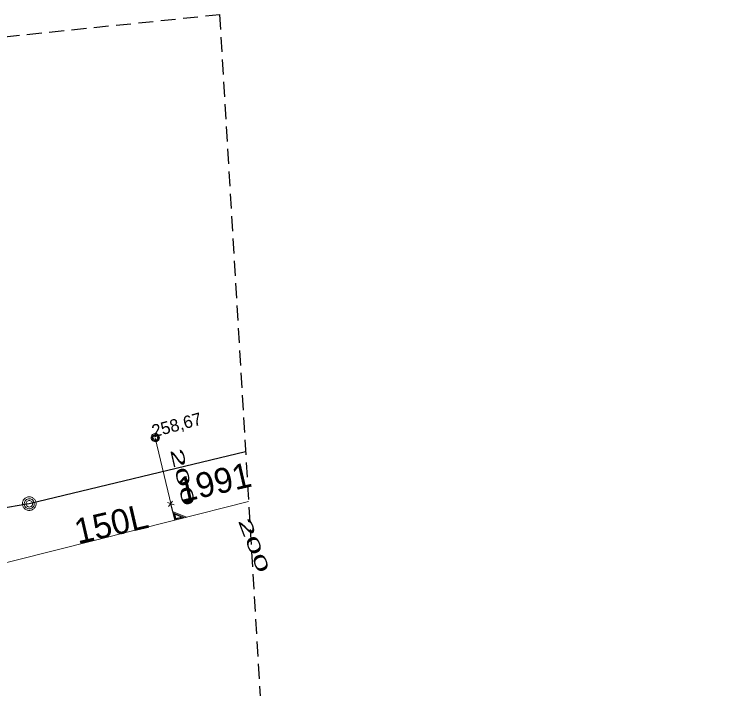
# Model space of a CAD drawing. Extents: x -732096 to -731933, y -1048703 to -1047964.
# Drawn here: x -732014.98 to -731968.39, y -1048007.32 to -1047964.04 of the extents above; entities that cross this region are included whole.
import ezdxf

# ---------------------------------------------------------------- set-up
doc = ezdxf.new("R2010")
doc.units = 0
doc.header["$LTSCALE"] = 0.32
doc.linetypes.add('MEDIUM_DASHED', pattern=[4.5, 3, -1.5])
doc.layers.add('1', color=7, linetype='Continuous')
for name, color, linetype, lineweight in [('18', 7, 'Continuous', 13), ('20', 7, 'Continuous', 13), ('49', 7, 'Continuous', 13), ('63', 7, 'MEDIUM_DASHED', 25), ('8', 7, 'Continuous', 13)]:
    doc.layers.add(name, color=color, linetype=linetype, lineweight=lineweight)

msp = doc.modelspace()

# ---------------------------------------------------------------- linework, layer by layer
at = {"layer": '18'}
for p, q in [((-732005.165, -1047995.377), (-732004.745, -1047995.523)), ((-732004.839, -1047995.281), (-732005.098, -1047995.624))]:
    msp.add_line(p, q, dxfattribs=at)
for points in [[(-732005.685, -1047991.207), (-732005.691, -1047991.151), (-732005.708, -1047991.098), (-732005.737, -1047991.049), (-732005.775, -1047991.008), (-732005.821, -1047990.976), (-732005.873, -1047990.954), (-732005.928, -1047990.943), (-732005.984, -1047990.945), (-732006.039, -1047990.958), (-732006.09, -1047990.983), (-732006.134, -1047991.018), (-732006.17, -1047991.061), (-732006.195, -1047991.111), (-732006.21, -1047991.166), (-732006.213, -1047991.222), (-732006.204, -1047991.277), (-732006.183, -1047991.33), (-732006.152, -1047991.376), (-732006.112, -1047991.415), (-732006.064, -1047991.445), (-732006.011, -1047991.464), (-732005.955, -1047991.471), (-732005.899, -1047991.467), (-732005.845, -1047991.45), (-732005.796, -1047991.423), (-732005.754, -1047991.385), (-732005.721, -1047991.34), (-732005.698, -1047991.289), (-732005.686, -1047991.234)], [(-732005.744, -1047991.21), (-732005.75, -1047991.161), (-732005.768, -1047991.115), (-732005.796, -1047991.074), (-732005.833, -1047991.041), (-732005.877, -1047991.019), (-732005.925, -1047991.007), (-732005.974, -1047991.007), (-732006.022, -1047991.019), (-732006.066, -1047991.042), (-732006.103, -1047991.075), (-732006.131, -1047991.116), (-732006.148, -1047991.163), (-732006.154, -1047991.212), (-732006.147, -1047991.261), (-732006.129, -1047991.307), (-732006.101, -1047991.347), (-732006.064, -1047991.38), (-732006.02, -1047991.402), (-732005.971, -1047991.414), (-732005.922, -1047991.413), (-732005.874, -1047991.401), (-732005.831, -1047991.377), (-732005.794, -1047991.344), (-732005.766, -1047991.303), (-732005.75, -1047991.256)], [(-732005.803, -1047991.214), (-732005.809, -1047991.172), (-732005.826, -1047991.134), (-732005.854, -1047991.103), (-732005.889, -1047991.08), (-732005.929, -1047991.069), (-732005.971, -1047991.069), (-732006.011, -1047991.081), (-732006.046, -1047991.104), (-732006.073, -1047991.136), (-732006.09, -1047991.174), (-732006.095, -1047991.215), (-732006.089, -1047991.257), (-732006.071, -1047991.294), (-732006.043, -1047991.326), (-732006.007, -1047991.348), (-732005.967, -1047991.359), (-732005.925, -1047991.358), (-732005.885, -1047991.345), (-732005.851, -1047991.322), (-732005.824, -1047991.289), (-732005.808, -1047991.251)]]:
    msp.add_lwpolyline(points, close=True, dxfattribs=at)
for points in [[(-732004.964, -1047995.446), (-732004.695, -1047996.509), (-732003.948, -1047996.32), (-732004.837, -1047995.948)], [(-732004.758, -1047996.05), (-732004.657, -1047996.453), (-732004.109, -1047996.315), (-732004.759, -1047996.049)], [(-732004.692, -1047996.12), (-732004.621, -1047996.402), (-732004.261, -1047996.311), (-732004.694, -1047996.121)]]:
    msp.add_lwpolyline(points, dxfattribs=at)
at = {"layer": '20'}
msp.add_lwpolyline([(-732017.52, -1047999.75), (-732004.701, -1047996.513), (-731999.955, -1047995.314)], dxfattribs=at)
msp.add_lwpolyline([(-732017.52, -1047999.75), (-732004.701, -1047996.513), (-731999.955, -1047995.314)], dxfattribs=at)
at = {"layer": '49'}
msp.add_line((-732005.949, -1047991.22), (-732004.701, -1047996.513), dxfattribs=at)
msp.add_line((-732005.949, -1047991.22), (-732004.701, -1047996.513), dxfattribs=at)
at = {"layer": '63'}
msp.add_lwpolyline([(-732040.436, -1048145.923), (-732073.567, -1048047.117), (-732073.568, -1048047.115), (-732073.568, -1048047.114), (-732073.568, -1048047.112), (-732060.033, -1047970.086), (-732060.033, -1047970.084), (-732060.032, -1047970.082), (-732060.031, -1047970.081), (-732060.029, -1047970.079), (-732060.028, -1047970.078), (-732060.026, -1047970.078), (-732060.024, -1047970.077), (-732001.831, -1047964.038), (-732001.829, -1047964.038), (-732001.827, -1047964.038), (-732001.825, -1047964.039), (-732001.823, -1047964.04), (-732001.822, -1047964.041), (-732001.821, -1047964.043), (-732001.82, -1047964.045), (-732001.82, -1047964.047), (-731997.077, -1048043.55), (-731968.389, -1048129.387)], dxfattribs=at)
at = {"layer": '8', "lineweight": 25}
for p, q in [((-732000.146, -1047992.114), (-732014.03, -1047995.459)), ((-732014.03, -1047995.459), (-732033.089, -1047998.739))]:
    msp.add_line(p, q, dxfattribs=at)
at = {"layer": '8'}
msp.add_lwpolyline([(-732013.598, -1047995.448), (-732013.601, -1047995.403), (-732013.608, -1047995.358), (-732013.62, -1047995.313), (-732013.636, -1047995.271), (-732013.657, -1047995.23), (-732013.682, -1047995.191), (-732013.711, -1047995.156), (-732013.743, -1047995.123), (-732013.779, -1047995.095), (-732013.816, -1047995.07), (-732013.858, -1047995.049), (-732013.901, -1047995.032), (-732013.945, -1047995.02), (-732013.99, -1047995.013), (-732014.036, -1047995.011), (-732014.081, -1047995.013), (-732014.127, -1047995.02), (-732014.171, -1047995.032), (-732014.214, -1047995.049), (-732014.255, -1047995.07), (-732014.293, -1047995.095), (-732014.329, -1047995.123), (-732014.361, -1047995.156), (-732014.39, -1047995.191), (-732014.415, -1047995.23), (-732014.436, -1047995.271), (-732014.451, -1047995.313), (-732014.464, -1047995.358), (-732014.471, -1047995.403), (-732014.473, -1047995.449), (-732014.471, -1047995.494), (-732014.464, -1047995.539), (-732014.451, -1047995.584), (-732014.436, -1047995.626), (-732014.415, -1047995.667), (-732014.39, -1047995.706), (-732014.361, -1047995.741), (-732014.329, -1047995.774), (-732014.293, -1047995.802), (-732014.255, -1047995.827), (-732014.214, -1047995.848), (-732014.171, -1047995.865), (-732014.127, -1047995.876), (-732014.081, -1047995.884), (-732014.036, -1047995.886), (-732013.99, -1047995.884), (-732013.945, -1047995.876), (-732013.901, -1047995.865), (-732013.858, -1047995.848), (-732013.816, -1047995.827), (-732013.779, -1047995.802), (-732013.743, -1047995.774), (-732013.711, -1047995.741), (-732013.682, -1047995.706), (-732013.657, -1047995.667), (-732013.636, -1047995.626), (-732013.62, -1047995.584), (-732013.608, -1047995.539), (-732013.601, -1047995.494), (-732013.598, -1047995.449)], dxfattribs=at)
for points in [[(-732013.712, -1047995.456), (-732013.718, -1047995.395), (-732013.736, -1047995.335), (-732013.765, -1047995.28), (-732013.804, -1047995.232), (-732013.851, -1047995.192), (-732013.905, -1047995.162), (-732013.964, -1047995.142), (-732014.026, -1047995.135), (-732014.088, -1047995.139), (-732014.147, -1047995.155), (-732014.203, -1047995.183), (-732014.253, -1047995.22), (-732014.294, -1047995.267), (-732014.326, -1047995.32), (-732014.346, -1047995.379), (-732014.356, -1047995.44), (-732014.353, -1047995.502), (-732014.338, -1047995.562), (-732014.312, -1047995.619), (-732014.276, -1047995.669), (-732014.23, -1047995.712), (-732014.178, -1047995.744), (-732014.12, -1047995.767), (-732014.059, -1047995.777), (-732013.997, -1047995.776), (-732013.936, -1047995.763), (-732013.879, -1047995.738), (-732013.828, -1047995.703), (-732013.784, -1047995.659), (-732013.75, -1047995.607), (-732013.726, -1047995.55), (-732013.714, -1047995.489)], [(-732013.826, -1047995.456), (-732013.831, -1047995.407), (-732013.848, -1047995.36), (-732013.877, -1047995.319), (-732013.915, -1047995.286), (-732013.959, -1047995.262), (-732014.007, -1047995.25), (-732014.057, -1047995.249), (-732014.105, -1047995.261), (-732014.15, -1047995.283), (-732014.188, -1047995.316), (-732014.217, -1047995.356), (-732014.236, -1047995.403), (-732014.243, -1047995.452), (-732014.238, -1047995.502), (-732014.221, -1047995.549), (-732014.194, -1047995.591), (-732014.157, -1047995.625), (-732014.114, -1047995.649), (-732014.066, -1047995.663), (-732014.016, -1047995.664), (-732013.967, -1047995.654), (-732013.922, -1047995.632), (-732013.883, -1047995.6), (-732013.853, -1047995.561), (-732013.834, -1047995.515), (-732013.826, -1047995.465)]]:
    msp.add_lwpolyline(points, close=True, dxfattribs=at)

# ---------------------------------------------------------------- texts
at = {"layer": '1'}
for s, height, rotation, p in [('258,67', 0.8, 15, (-732006.051, -1047991.196)), ('1991', 1.6, 13, (-732004.298, -1047995.394)), ('150L', 1.6, 13, (-732010.915, -1047998.044))]:
    msp.add_text(s, height=height, rotation=rotation, dxfattribs=at).set_placement(p)
for rotation, width, p in [(283, 2.1, (-732004.997, -1047992.001)), (291, 2.05, (-732000.648, -1047996.552))]:
    msp.add_text('200 ', height=0.8, rotation=rotation, dxfattribs=dict(at, width=width)).set_placement(p)

doc.saveas('drawing.dxf')
